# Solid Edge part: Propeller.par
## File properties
Author: m_hel
Template: iso metric part.par
Last saved by: m_hel
Revision: 9
Application: Solid Edge
Density: 1,050e+04 kg/m^3
Accuracy: 0,990
Username: m_hel
Material: Silver
Face Style: Silver
Fill Style: ANSI31(Iron)
Virtual Style: Silver
Grouping: Metals\Other metals
LibraryName: Materials
Coef. of Thermal Exp: 1e-05
Thermal Conductivity: 419.0
Specific Heat: 234.0
Modulus of Elasticity: 75842327000.0
Poisson's Ratio: 0.38
Yield Stress: 303369308.0
Ultimate Stress: 344737850.0
Elongation: 0.0
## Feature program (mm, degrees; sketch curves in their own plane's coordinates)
sketch for "unnamed Protrusion 1" plane through (0, 0, 0) normal (0, -1, 0) x-axis (1, 0, 0)
  circle centre (0, 0) radius 25
extrude "unnamed Protrusion 1" add finite 70 along +normal
sketch for "unnamed Cutout 1" plane through (0, 0, 0) normal (0, 1, 0) x-axis (-1, 0, 0)
  circle centre (0, 0) radius 15
extrude "unnamed Cutout 1" cut through along -normal
sketch for "unnamed RevolvedProtrusion 1" plane through (0, 0, 0) normal (1, 0, 0) x-axis (0, 1, 0)
  line (-70, 55) -> (10, 55)
  line (10, 53) -> (10, 55)
  line (0, 45) -> (10, 53)
  line (0, 45) -> (-60, 45)
  line (-60, 45) -> (-70, 53)
  line (-70, 53) -> (-70, 55)
revolve "unnamed RevolvedProtrusion 1" add finite 360 deg
sketch for "unnamed Protrusion 2" plane through (0, -70, 0) normal (0, -1, 0) x-axis (1, 0, 0)
  line (-5, 15.6) -> (5, 15.6)
  line (5, 15.6) -> (5, 53)
  line (5, 53) -> (-5, 53)
  line (-5, 53) -> (-5, 15.6)
  dimension (linear) = 5
  dimension (linear) = 5
extrude "unnamed Protrusion 2" add to key point along -normal
thicken "Thicken_13"  Distance1 = 3 mm
pattern "unnamed Pattern 1" of "Thicken_13", "unnamed Protrusion 2"
extrude "unnamed Protrusion 3" add finite 70
thicken "unnamed Thicken 1"
extrude "unnamed Protrusion 4" add finite 70
thicken "unnamed Thicken 2"
extrude "unnamed Protrusion 5" add finite 70
thicken "unnamed Thicken 3"
sketch for "unnamed Cutout 2" #1 plane through (0, 0, 0) normal (0, 1, 0) x-axis (-1, 0, 0)
  arc centre (0, 0) radius 45 from (-44.7214, 5) to (-5, 44.7214) cw
  line (-5, 24.4949) -> (-5, 44.7214)
  arc centre (0, 0) radius 25 from (-5, 24.4949) to (-24.4949, 5) ccw
  line (-44.7214, 5) -> (-24.4949, 5)
sketch for "unnamed Cutout 2" #2 plane through (0, 0, 0) normal (0, 1, 0) x-axis (-1, 0, 0)
  line (5, 44.7214) -> (5, 24.4949)
  arc centre (0, 0) radius 25 from (24.4949, 5) to (5, 24.4949) ccw
  line (24.4949, 5) -> (44.7214, 5)
  arc centre (0, 0) radius 45 from (5, 44.7214) to (44.7214, 5) cw
sketch for "unnamed Cutout 2" #3 plane through (0, 0, 0) normal (0, 1, 0) x-axis (-1, 0, 0)
  arc centre (0, 0) radius 25 from (5, -24.4949) to (24.4949, -5) ccw
  line (44.7214, -5) -> (24.4949, -5)
  arc centre (0, 0) radius 45 from (44.7214, -5) to (5, -44.7214) cw
  line (5, -24.4949) -> (5, -44.7214)
sketch for "unnamed Cutout 2" #4 plane through (0, 0, 0) normal (0, 1, 0) x-axis (-1, 0, 0)
  line (-5, -44.7214) -> (-5, -24.4949)
  arc centre (0, 0) radius 25 from (-24.4949, -5) to (-5, -24.4949) ccw
  line (-24.4949, -5) -> (-44.7214, -5)
  arc centre (0, 0) radius 45 from (-5, -44.7214) to (-44.7214, -5) cw
extrude "unnamed Cutout 2" cut through along -normal
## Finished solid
Body 1: sheet body, 1 face, 2 edges, 2 vertices.
  Faces by surface: spline 1
  Edges by curve: curve on surface 2
Body 2: sheet body, 1 face, 2 edges, 2 vertices.
  Faces by surface: spline 1
  Edges by curve: curve on surface 2
Body 3: sheet body, 1 face, 2 edges, 2 vertices.
  Faces by surface: spline 1
  Edges by curve: curve on surface 2
Body 4: sheet body, 1 face, 2 edges, 2 vertices.
  Faces by surface: spline 1
  Edges by curve: curve on surface 2
Body 5: solid body, 42 faces, 101 edges, 60 vertices.
  Faces by surface: spline 12, plane 11, cylinder 10, cone 5, offset 4
  Edges by curve: line 32, circle 29, intersection 24, curve on surface 16
Bounding box of the edges (mm; curved faces can reach further): 530.432 x 162.833 x 530.432, from (-265.2159, -99.1714, -265.2159) to (265.2159, 63.662, 265.2159).
Cylindrical faces by radius (mm): R15 x1, R25 x4, R45 x4, R55 x1
Conical faces (half-angle, radius in mm at the cone's reference point): 38.6598 deg R45 x4, 38.6598 deg R53 x1
Planar faces by outward normal: +x 2, +y 2, +z 2, -x 2, -y 1, -z 2
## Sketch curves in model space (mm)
spline (113.7698, 70.4514, 0) -> (4.8502, -34.0615, 0) -> (-133.0003, -103.6396, 0)
spline (-39.3587, 0, 38.4173) -> (8.7908, 0, 264.8017) -> (35.4599, 0, 42.0428)
line (0, -6.3045, 0) -> (0, 1.7013, 0)
line (0, -60, 45) -> (0, -70, 53)
line (0, -70, 53) -> (0, -70, 55)
line (0, -70, 55) -> (0, 10, 55)
line (0, 10, 53) -> (0, 10, 55)
line (0, 0, 45) -> (0, 10, 53)
line (0, 0, 45) -> (0, -60, 45)
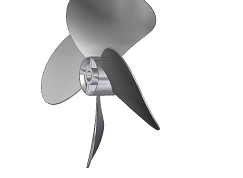
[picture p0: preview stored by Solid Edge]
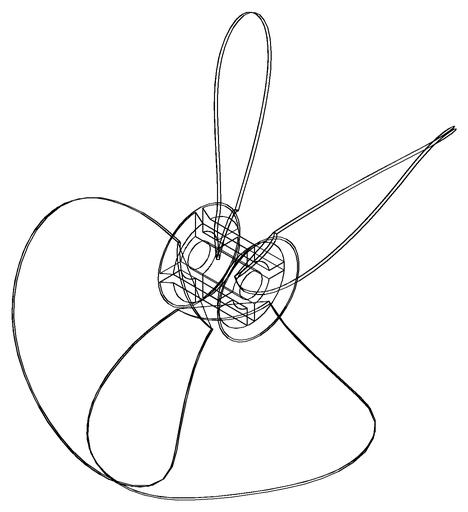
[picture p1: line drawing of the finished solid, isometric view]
